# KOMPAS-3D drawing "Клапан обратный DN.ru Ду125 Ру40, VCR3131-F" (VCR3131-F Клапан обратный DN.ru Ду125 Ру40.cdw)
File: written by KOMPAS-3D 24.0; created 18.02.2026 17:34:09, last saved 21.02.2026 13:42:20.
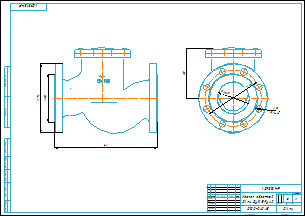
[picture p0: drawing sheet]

Document properties: art: D100-04045; Автор: R2D2; Форматы листов документа: A2; Полное имя файла: VCR3131-F Клапан обратный DN.ru Ду125 Ру40.m3d; Масса: 38; Наименование: Клапан обратный DN.ru Ду125 Ру40; Количество листов документа: 1; Примечание: D100-04045

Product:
- Part/product: Клапан обратный DN.ru Ду125 Ру40  | designation VCR3131-F
    Масса: 38
    Форматы листов документа: A2
    Примечание: D100-04045
    additional columns: D100-04045

Views: Вид 1, Спереди, Проекционный вид 2
Referenced files in E:\Работа\Зайцев\VCR3131-F Клапан обратный DN.ru Ду15-300\DN125\: VCR3131-F Клапан обратный DN.ru Ду125 Ру40.m3d
Referenced files in E:\Работа\Зайцев\Для компаса\: чертеж DN.ru А3.cdt
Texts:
  VCR3131-F
  чертеж DN.ru А3.cdt
  Клапан обратный
  DN.ru Ду125 Ру40
  prop
  Клапан обратный DN.ru Ду125 Ру40
  VCR3131-F Клапан обратный DN.ru Ду125 Ру40
Dimensions and other numbers on the sheet: 0; 3; 2; 4; 195; 125; 220; 26; 8 отв.; 400; 270; 188; 1:2; 1; 38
